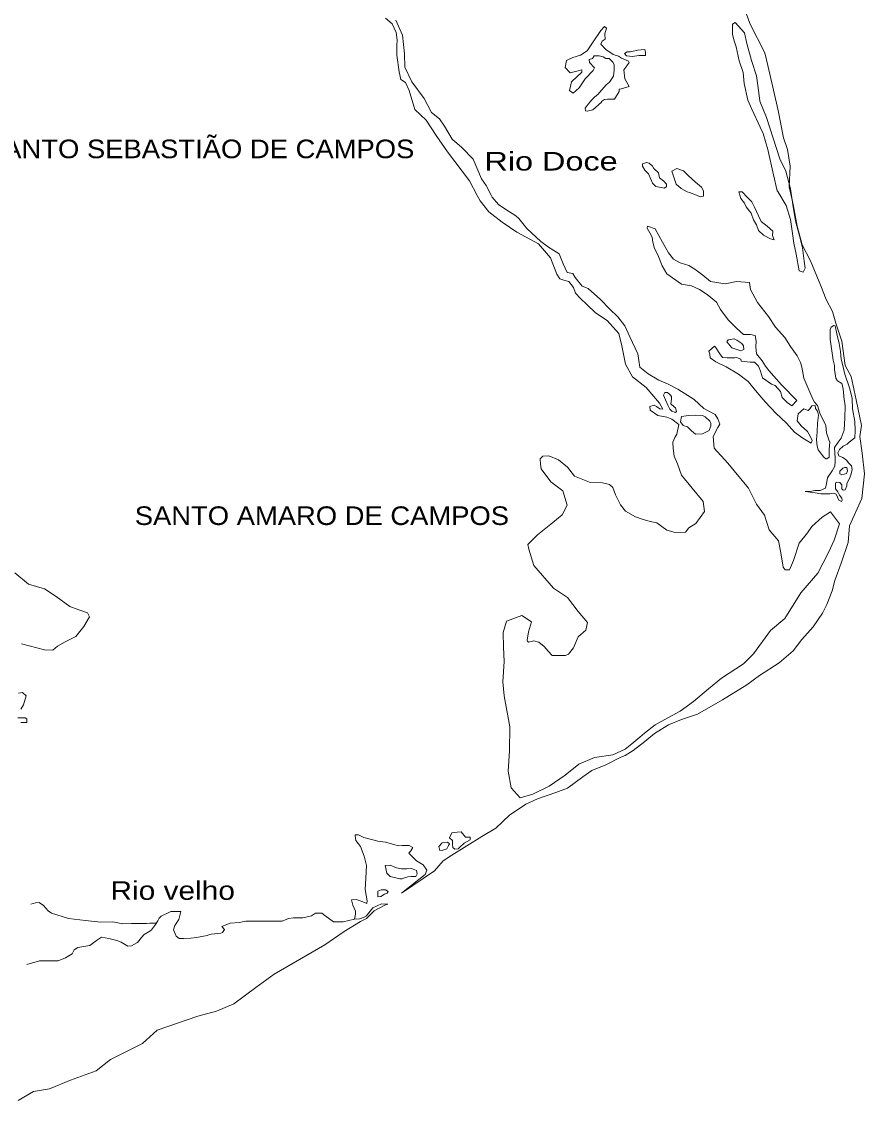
# Model space of a CAD drawing. Extents: x 47169 to 972804, y 7447977 to 9608469.
# Drawn here: x 267595 to 296306, y 7548738 to 7585503 of the extents above; entities that cross this region are included whole.
import ezdxf

# ---------------------------------------------------------------- set-up
doc = ezdxf.new("R2010")
doc.units = 0
doc.header["$LTSCALE"] = 270
doc.layers.add('1', color=7, linetype='Continuous', lineweight=13)
doc.layers.add('3', color=7, linetype='Continuous')

msp = doc.modelspace()

# ---------------------------------------------------------------- linework, layer by layer
at = {"layer": '1'}
for points in [[(278978.4, 7557599.3), (278967.3, 7557654.6), (278955.1, 7557787.3), (279068.7, 7557788.9), (279255.7, 7557702.9), (279732.4, 7557576.7), (279991.1, 7557536), (280270.9, 7557462.4), (280426.5, 7557409.2), (280560.5, 7557422.1), (280798, 7557425.4), (280922.8, 7557360.7), (280852.2, 7557237.9), (280791.3, 7557159.5), (281042.6, 7556908.2), (281271.7, 7556767.4), (281398.2, 7556580.9), (281338.3, 7556436.1), (280541.8, 7555804.7), (281656.5, 7556562.3), (281961.6, 7556898.9), (282248, 7557091.1), (283271.5, 7557736.6), (283752.8, 7558020.2), (284211.4, 7558458.4), (284774.2, 7558831.7), (285174.3, 7559014.4), (285790.9, 7559233.2), (286191.5, 7559382.6), (286712.9, 7559766.3), (287019.8, 7559980.9), (287502.4, 7560175.7), (288004.9, 7560437.2), (288159, 7560494.7), (288425.2, 7560664.4), (288823.8, 7560968.8), (289150.6, 7561239), (289632, 7561533.4), (290073.6, 7561716.5), (290618.4, 7561901), (291469.1, 7562388.5), (292298.8, 7562897.9), (292728.4, 7563213.7), (293404.2, 7563654.5), (293874, 7564059.4), (294168.4, 7564450.8), (294555.3, 7564876.8), (294879.7, 7565346.2), (295030.9, 7565636.1), (295210.7, 7566103.6), (295299.1, 7566459.1), (295518.7, 7567049), (295747.2, 7567749.7), (295801.9, 7568315.2), (296213.4, 7569250.9), (296305.8, 7570093.8), (296234.8, 7570790.6), (296144.8, 7571365.4), (296201.9, 7571742.7), (296025.3, 7572615.4), (295849.8, 7573410.5), (295648.6, 7573784.5), (295534.6, 7574613.7), (295330.4, 7575220.2), (295221.9, 7575617.5), (294999.5, 7576035.5), (294817.8, 7576498.3), (294465.7, 7577346.5), (294189.8, 7577896.7), (294016.2, 7578525.8), (293882.6, 7579266.1), (293776.4, 7579721), (293740.3, 7579873.4), (293772.6, 7580571.6), (293682.5, 7581146.3), (293553.2, 7581543.4), (293365.4, 7582471.2), (293156.6, 7583421), (293014.6, 7584006.2), (292915.9, 7584436.8), (292406.5, 7585438), (292224, 7585945.1)], [(279993.4, 7585614.8), (280223.5, 7585429.6), (280351.8, 7585132.4), (280386.4, 7584867), (280378.5, 7584689.7), (280383.1, 7584357.4)], [(288156.1, 7560705.1), (288380.9, 7560885.3), (288656.5, 7561121.6), (288819.9, 7561256.7), (289177.6, 7561538.4), (289505.6, 7561720), (290028.5, 7562003.9), (290488.8, 7562331.2), (290999.5, 7562758.9), (291438.6, 7563130.2), (292186.1, 7563616.3), (292522.5, 7563953), (293111.1, 7564747.1), (293591, 7565163.2), (294137.4, 7566034.2), (294717.4, 7566706.3), (295080.2, 7567408.8), (295271, 7567832.1), (295460, 7568388.4), (295155.2, 7568794.2), (294868.3, 7568613.3), (294510.8, 7568298.5), (294369.1, 7568075.2), (294084.4, 7567728.1), (293895.8, 7567138.6), (293755.4, 7566815.6), (293610.8, 7566813.7), (293537.2, 7566912.5), (293458.5, 7567398.8), (293380.9, 7567807.5), (293055.8, 7568179.8), (292904.5, 7568687.3), (292631, 7569060.3), (292355.3, 7569599.4), (291651.8, 7570454.1), (291190.4, 7570968.5), (291154.2, 7571366.8), (291315.5, 7571667.9), (291376, 7571779.5), (291311.6, 7571966.9), (291227, 7572109.8), (290831.7, 7572315), (290507.3, 7572620.9), (289954.9, 7572979), (289621.9, 7573151.8), (289299.8, 7573280.5), (288935.2, 7573497.1), (288653.2, 7573725.9), (288585.1, 7574179.1), (288318.9, 7574762.6), (288148.6, 7575136.9), (287906.8, 7575443.8), (287624, 7575716.9), (287320, 7576034), (286891.3, 7576404.9), (286693.7, 7576490.8), (286452, 7576786.6), (286377.9, 7576918.5), (286181.1, 7576949.1), (286042.7, 7577246.3), (285903.7, 7577587.8), (285549.2, 7577815.6), (285288.1, 7578011.4), (284806.7, 7578447.9), (284533.3, 7578787.6), (284428.5, 7578885.8), (284094.8, 7579102.8), (283844.5, 7579265.5), (283623.9, 7579517.3), (283588.9, 7579585.5), (283422.1, 7579913.3), (283263.9, 7580143.7), (282975.5, 7580815.4), (282587.6, 7581208.9), (282263.2, 7581492.4), (281998.5, 7581942.9), (281829.8, 7582184.3), (281557.9, 7582402), (281313.4, 7582886), (280892.1, 7583445.1), (280647.3, 7583951.3), (280641, 7584405.3), (280570.3, 7585035.7), (280346, 7585553.2)], [(293797.1, 7579721.3), (293782.5, 7579807.5), (293630, 7580403.6), (293428.2, 7580821.8), (292965.2, 7582233.5), (292740.8, 7582795.4), (292706.2, 7583071.8), (292626.2, 7583657.8), (292454, 7584176.1), (292301.5, 7584761.1), (292224.5, 7585114.5), (291899.2, 7585475.7), (291806.9, 7585419.1), (291808.5, 7585297.3), (291811.5, 7585064.8), (291866.1, 7584844), (291941.1, 7584645.6)], [(280383.1, 7584357.4), (280453, 7583793.5), (280518.7, 7583528.6), (280675.1, 7583431.1), (280792.7, 7583155.8), (280987.8, 7582505), (281375.3, 7582144.8), (281713.4, 7581617.8), (282103.5, 7581069.3), (282851.3, 7580071.6), (283112.4, 7579579), (283212.1, 7579389.9), (283506.7, 7579017.3), (283966.3, 7578669.1), (284467.2, 7578321.5), (285206.5, 7577932.8), (285616.1, 7577451), (285830.3, 7576900), (285925.5, 7576735.2), (286070.8, 7576692.9), (286236.9, 7576639.7), (286394.6, 7576442.5), (286459.3, 7576244), (286637.4, 7576069.2)], [(291941.1, 7584645.6), (292040.5, 7584159.6), (292180.1, 7583762.7), (292205.6, 7583397.5), (292337.2, 7582823.3), (292475.6, 7582515), (292752.3, 7581909.5)], [(292752.3, 7581909.5), (292858.6, 7581689.4), (293020.7, 7581148.8), (293207.8, 7580276.3), (293338.9, 7579735.3), (293351.6, 7579715.5)], [(290827.5, 7579682.5), (290826.8, 7579735.6), (290752.8, 7579856.5), (290554.1, 7580031.1), (290313.4, 7580249.4), (290145.9, 7580413.3), (289917.3, 7580498.9), (289742.7, 7580408), (289817.9, 7580198.5), (289893.3, 7579967), (290060.7, 7579814.1), (290268.9, 7579706.1), (290351, 7579676.2), (290591, 7579588.5)], [(290591, 7579588.5), (290715.7, 7579534.8), (290829.1, 7579558.4), (290827.5, 7579682.5)], [(293351.6, 7579715.5), (293645.2, 7579240.9), (293785.9, 7578755.4), (293854.1, 7578280), (293899.7, 7577948.4), (293977, 7577572.8), (294087.6, 7577009.4), (294222.5, 7576966.8), (294282.8, 7577100.5), (294248.7, 7577343.7), (294191.1, 7577797.1), (294092.8, 7578205.6), (293962.1, 7578713.4), (293872.3, 7579266), (293797.1, 7579721.3)], [(293790.5, 7574424.9), (293590.1, 7574732.5), (293275.4, 7575093.8), (293032.9, 7575456.2), (292665, 7575927.6), (292421.6, 7576367.4), (292387.4, 7576610.7), (291952.8, 7576649.3), (291561.1, 7576566.6), (291063.9, 7576648.7), (290802.7, 7576855.6), (290531.2, 7577062.5), (290322.8, 7577192.7), (290032.2, 7577277.4), (289803.1, 7577407.3), (289634.8, 7577626.6), (289423.3, 7577989.3), (289179.5, 7578440.1), (288920, 7578525.3), (288910.5, 7578458.7), (288995.3, 7578304.8), (289080, 7578150.8), (289102.9, 7577985), (289157.5, 7577764.2), (289263.7, 7577555.2), (289413.4, 7577180.6), (289572, 7576905.8), (290072.8, 7576558), (290414.7, 7576496.1), (290685, 7576377.9), (290945.7, 7576204.1), (291269.5, 7575942.5), (291407.2, 7575689.6), (291659.9, 7575338.5), (291953, 7575054.4), (292183.2, 7574835.9), (292420.9, 7574839), (292586.7, 7574808), (292620.3, 7574609), (292602.1, 7574420.5), (292625.9, 7574177.2), (292825.4, 7573936.1), (292931.1, 7573760.3), (293046.6, 7573617.8), (293476.7, 7573125), (294000.4, 7572589.2), (293837.4, 7572409.8), (293670.6, 7572518.4), (293503, 7572693.4), (293448.8, 7572892.1), (293270.4, 7573100.2), (293135.5, 7573142.7), (292833, 7573360.3), (292767.9, 7573592), (292693.4, 7573757.2), (292557.2, 7573899.4), (292412.6, 7573897.5), (292102.2, 7573926.6), (292090.8, 7574004), (291945.4, 7574057.5), (291893.9, 7574045.7), (291635.6, 7574042.3), (291470.1, 7574051.2), (291375.4, 7574182.9), (291227.8, 7574402.5), (291196.2, 7574446.4), (291002.2, 7574266.6), (291034.5, 7574167.3), (291046.5, 7574045.7), (291244.7, 7573904.3), (291598.3, 7573731.7), (292015, 7573482.5), (292349, 7573232.1), (292653.5, 7572859.5), (292926.3, 7572541.9), (293282.7, 7572158.9), (293648.7, 7571820.4), (293921.4, 7571513.8), (294203, 7571307), (294494.6, 7571133.6), (294524.5, 7571222.6), (294460.5, 7571376.8), (294365.5, 7571530.7), (294145.9, 7571727.2), (294019.6, 7571902.7), (294047.6, 7572135.7), (294241.7, 7572304.3), (294387.1, 7572250.9), (294448.4, 7572307), (294516.9, 7572406.9), (294625.9, 7572420.6), (294639.5, 7572320.3), (294703.1, 7572229.2), (294740.5, 7572089.3), (294713, 7571823.1), (294696.2, 7571523.9), (294668.8, 7571246.6), (294692.2, 7571036.5), (294735.2, 7570904.2), (294924.3, 7570663), (294987.2, 7570597.3)], [(286637.4, 7576069.2), (286846.9, 7575861.5), (287140.1, 7575577.5), (287546.7, 7575317.1), (287935.1, 7574868.2), (288044.1, 7574448.8), (288166, 7573830.2), (288409.5, 7573401.5), (288869.1, 7573031), (289330.9, 7572494.5), (289436.9, 7572296.5), (289333.4, 7572306.2), (289218.8, 7572382.2), (289145.9, 7572425.6), (289001.7, 7572390.4), (289003.4, 7572257.5), (289274.4, 7572083.9), (289574.9, 7572021.5), (289741.1, 7571957.2), (289981.2, 7571772.1), (289913.3, 7571439), (289852.8, 7571327.4), (289782.5, 7571171.4), (289785.5, 7570949.9), (289830.2, 7570695.8), (289937, 7570431.4), (290076.4, 7570045.6), (290433.5, 7569607.3), (290811.5, 7569147.1), (290857.4, 7568804.4), (290563.2, 7568401.7), (290327.5, 7568254.6), (290205.6, 7568098), (289864.8, 7568093.4), (289574.5, 7568167.1), (289230.3, 7568417.2), (289002.3, 7568469.6), (288732.7, 7568543.5), (288504.3, 7568629.1), (288171.1, 7568824), (287992.6, 7569032), (287822.8, 7569373.1), (287736.7, 7569626.7), (287621.7, 7569724.8), (287383.3, 7569788.1), (286938.8, 7569804.2), (286429.8, 7570007.8), (286188, 7570314.7), (285884.9, 7570565.3), (285552.4, 7570704.8), (285356.3, 7570691.1), (285264.5, 7570601.2), (285266.9, 7570424), (285300.2, 7570258.4), (285626.4, 7569819.7), (286033.5, 7569515.1), (286184.8, 7569018.8), (286013.6, 7568695.2), (285625.3, 7568379.8), (285165.4, 7568008.1), (284839.3, 7567682.4), (284872.4, 7567527.8), (285045.3, 7566965.3), (285716.8, 7566199.1), (286196.4, 7565873.3), (286554, 7565401.9), (286868.9, 7565029.5), (286810.5, 7564762.9), (286555.3, 7564538), (286395.2, 7564159.2), (286222.5, 7563946.4), (286119.9, 7563900.7), (285665.5, 7563894.6), (285529.1, 7564047.8), (285392.8, 7564201), (285215.1, 7564353.6), (285049.3, 7564395.7), (284864, 7564348.8), (284832.4, 7564392.7), (284821.7, 7564425.8), (284859.2, 7564703.2), (284968.1, 7565048.1), (284634.6, 7565265), (284110.5, 7565069.6), (284002.2, 7564680.4), (284009, 7564182.1), (284036.4, 7563695.1), (283994.1, 7563007.8), (284031.8, 7562521), (284232.1, 7561471.5), (284212.3, 7560651.5), (284170.3, 7559953.2), (284270.9, 7559389.7), (284575, 7559050.5), (285006.9, 7559178.2), (285571, 7559451.7), (286113.2, 7559824.6), (286583.2, 7560196.5), (287106.7, 7560425.1), (287735.4, 7560511.1), (288156.1, 7560705.1)], [(294987.2, 7570597.3), (295028.5, 7570597.9), (295100.1, 7570654.2), (295109.7, 7570709.7), (295108.1, 7570831.5), (295107, 7570920), (295124.3, 7571175), (295092.3, 7571252.1), (295017, 7571483.7), (294993.1, 7571738.2), (294791.3, 7572156.4), (294705.2, 7572421.1), (294610.8, 7572530.6), (294547.4, 7572640.6), (294238.5, 7573345.4), (294171.7, 7573721.1), (294128.2, 7573886.6), (294011.6, 7574106.6), (293790.5, 7574424.9)], [(267362.5, 7566714.7), (267833, 7566333.9), (268372.6, 7566175.7), (268769, 7565915.6), (269238.9, 7565568), (269540.1, 7565461.7), (269841.2, 7565355.3), (269905.1, 7565223.3), (269713.7, 7564888.2), (269439.7, 7564551.9), (269080.8, 7564369.4), (268814.4, 7564221.5), (268661.5, 7564086.3), (268372.2, 7564093.1), (267594.5, 7564292.2)], [(267484.9, 7562617.9), (267629.1, 7562642.1), (267754.8, 7562522.1), (267656, 7562221.6), (267565.2, 7562076.2)], [(267466.3, 7561775.7), (267714.2, 7561779.4), (267776.8, 7561736), (267777.7, 7561669.5), (267778.6, 7561614.1), (267665, 7561612.5), (267572, 7561611.1)], [(267483.8, 7548737.7), (268005.6, 7549044.5), (268551.2, 7549130.2), (269258.9, 7549428.6), (270131.5, 7549740.5), (270621.1, 7550135.4), (271717.6, 7550672), (272216.6, 7551133.5), (273603, 7551607.7), (274230.1, 7551782.9), (274825.2, 7552024.1), (275570.6, 7552588.6), (276193.8, 7553040.6), (277924, 7554039.9), (278588.6, 7554492.4), (279141.2, 7554832.5), (279346.2, 7554935), (279600.7, 7555193.4), (279990.1, 7555398.2), (280072.3, 7555421.5), (279855.3, 7555440.6), (279557.8, 7555303.5), (279375.3, 7555068.4), (279345, 7555023.6), (279242.5, 7554966.8), (279139.8, 7554932.1), (279109, 7554920.6), (278933.5, 7554918.2), (278972.5, 7555084.9), (278971.1, 7555184.5), (278875.2, 7555393.6), (278831.5, 7555570.2), (278996.4, 7555583.6), (279162.4, 7555530.6), (279359.7, 7555444.8), (279368.6, 7555544.6), (279301.3, 7555931.3), (279316.6, 7556308.1), (279341.5, 7556740.5), (279264.8, 7557060.6), (279136.2, 7557391.1), (278978.4, 7557599.3)], [(272184.3, 7554777.4), (271967.6, 7554774.2), (271854, 7554772.6), (271637.3, 7554769.5), (271338, 7554765.1), (271038.7, 7554760.7), (270707.4, 7554822.4), (270294.6, 7554816.3), (269777.7, 7554864.2), (269198.6, 7554933.2), (268617.7, 7555124), (268503, 7555199.9), (268345.5, 7555374.8), (268199.4, 7555483.4), (268065.4, 7555470.4), (267911.2, 7555423.8)], [(278933.5, 7554918.2), (278552.9, 7554824.2), (278222.7, 7554819.5), (277920.2, 7555036.8), (277826.1, 7555124.1), (277609.3, 7555121), (277476.4, 7555030.5), (277178.1, 7554959.8), (276858.1, 7554955.3), (276682.8, 7554941.7), (276467.3, 7554850), (276199, 7554846.2), (275941, 7554842.5), (275600.2, 7554848.7), (275239, 7554843.6), (275012.6, 7554796), (274703.1, 7554780.5), (274610.7, 7554745.9), (274415.7, 7554665.6), (274510, 7554567.3), (274439.4, 7554455.5), (274377.8, 7554432.4), (274047.8, 7554405.5), (273996.4, 7554393.7), (273914.3, 7554359.3), (273554, 7554287.7), (273358.2, 7554262.7), (273120.9, 7554259.2), (272966.1, 7554257), (272861.7, 7554333), (272765.7, 7554553.2), (272815.2, 7554697.9), (272956.8, 7554899.4), (273014.7, 7555177.1), (272911.5, 7555175.6), (272684.4, 7555172.3), (272346.1, 7555012.4), (272285.1, 7554945), (272234.8, 7554855.7), (272154, 7554732.7), (272022.4, 7554553.5), (271961.1, 7554508.3), (271766.6, 7554394.7), (271675.2, 7554293.7), (271543.6, 7554114.5), (271338.8, 7554000.8), (271214.9, 7553999), (270986, 7554128.6), (270840.5, 7554192.9), (270571.2, 7554255.4), (270322.8, 7554296.1), (270149, 7554182.8), (269924.4, 7554013.4), (269512.4, 7553951.9), (269389.7, 7553872.6), (269319.4, 7553738.6), (269094.4, 7553591.3), (268837.7, 7553498.9), (268507.5, 7553494), (268208.2, 7553489.6), (267776.3, 7553372.5)]]:
    msp.add_lwpolyline(points, dxfattribs=at)
for points in [[(287624.2, 7583436.7), (287511.7, 7583346.6), (287226.5, 7583021.6), (287124.1, 7582942.7), (287022.1, 7582841.7), (286900.1, 7582685), (286798.5, 7582550.7), (286799.7, 7582462.1), (286861.8, 7582451.9), (287057.7, 7582498.8), (287354.1, 7582757.5), (287353.8, 7582779.7), (287456.3, 7582847.5), (287559.5, 7582859.9), (287631.9, 7582860.9), (287797.3, 7582863.1), (287949, 7583119.9), (287947.9, 7583197.4), (288020.2, 7583209.4), (288288, 7583290.5), (288139.7, 7583554.4), (288115, 7583853.1), (288216.5, 7583998.4), (288297.7, 7584110.2), (288266.1, 7584154.1), (288027, 7584250.6), (287932.9, 7584326.9), (287746, 7584379.8), (287495.5, 7584553.7), (287327.7, 7584728.6), (287367.6, 7584839.9), (287470.1, 7584907.7), (287467.8, 7585084.9), (287516.9, 7585273.9), (287454, 7585339.5), (287331.9, 7585193.9), (287068.1, 7584813.8), (286865.4, 7584500.9), (286639.9, 7584353.9), (286371.9, 7584283.9), (286156.1, 7584181.3), (286107.7, 7583937), (286286, 7583751.1), (286512.7, 7583809.5), (286677.6, 7583856), (286678.6, 7583778.5), (286331.4, 7583452.6), (286263, 7583152.7), (286388.3, 7583065.8), (286592.7, 7583245.7), (286795.5, 7583547.5), (287070.8, 7583839.1), (287110.9, 7583928.3), (286943.1, 7584103.2), (286931.3, 7584213.9), (287044.6, 7584248.6), (287105.4, 7584338), (287270.9, 7584340.2), (287405.9, 7584297.7), (287499.7, 7584243.6), (287613.4, 7584245.1), (287739.1, 7584125), (287781.6, 7584036.9), (287784.2, 7583848.7), (287756, 7583637.9)], [(288408.8, 7584311.1), (288201.7, 7584330.5), (288138.5, 7584418.2), (288220.5, 7584474.7), (288334.2, 7584476.2), (288571.4, 7584523.7), (288829.6, 7584549.3), (288851.6, 7584449.9), (288853, 7584350.2), (288625.5, 7584347.2)], [(288822.2, 7580440.1), (288748, 7580572), (288747, 7580649.5), (288880.8, 7580695.6), (288974.1, 7580674.7), (289089.2, 7580576.5), (289131.5, 7580499.6), (289288.6, 7580346.6), (289321.9, 7580180.9), (289468.2, 7580061), (289562.5, 7579962.6), (289563.6, 7579885.1), (289491.9, 7579828.7), (289201.8, 7579880.3), (289086.5, 7580000.6), (289033, 7580132.8), (288948, 7580308.9)], [(292992.8, 7578534.6), (293191.4, 7578360), (293172.7, 7578215.8), (293226.4, 7578061.4), (293101.7, 7578104.1), (292872.8, 7578222.9), (292694.9, 7578386.8), (292630.5, 7578574.2), (292524.8, 7578750), (292449.5, 7578970.5), (292386.5, 7579047.2), (292281.3, 7579189.9), (292217.7, 7579310.9), (292091.4, 7579475.3), (292026.5, 7579696), (292140.2, 7579697.5), (292307.9, 7579522.5), (292475.5, 7579358.5), (292560.5, 7579182.4), (292698.8, 7578885.2), (292794.4, 7578687.1)], [(294288.7, 7569491.8), (294453.9, 7569493.9), (294618.9, 7569518.2), (294794.5, 7569520.5), (294979.4, 7569600.4), (295018.7, 7569756), (295047.1, 7569955.7), (295077.4, 7570011.5), (295138.4, 7570089.8), (295209.4, 7570190.4), (295300.4, 7570346.6), (295308.4, 7570523.9), (295307.1, 7570623.6), (295294.5, 7570800.6), (295292.1, 7570988.9), (295413.7, 7571167.7), (295515.3, 7571301.9), (295615, 7571580.1), (295640.6, 7572001.3), (295645.7, 7572411.1), (295600.5, 7572709.6), (295598.2, 7572886.8), (295565.2, 7573041.4), (295532.5, 7573173.9), (295386.7, 7573260.6), (295333.9, 7573348.5), (295288.7, 7573647), (295287, 7573779.8), (295243.2, 7573967.5), (295141.1, 7574675), (295138.6, 7574863.3), (295136.8, 7575007.2), (295177.1, 7575085.3), (295259, 7575141.7), (295310.9, 7575131.3), (295365.9, 7574866.2), (295442.6, 7574535), (295487.5, 7574258.7), (295511.6, 7573993.2), (295576.9, 7573739.3), (295631.4, 7573518.5), (295803.5, 7572989.1), (295890.5, 7572657.9), (295905.4, 7572303.7), (295983.2, 7571872.8), (295987.2, 7571562.7), (295980, 7571319), (295785.6, 7571172.5), (295714.2, 7571105.1), (295580.7, 7571036.9), (295458.2, 7570924.6), (295397.8, 7570802), (295430.1, 7570702.7), (295575.4, 7570649.2), (295700.5, 7570562.2), (295774.3, 7570452.4), (295868.4, 7570365), (295890.6, 7570243.5), (295841.5, 7570043.5), (295801.6, 7569932.2), (295710.8, 7569765), (295712, 7569676.4), (295651.7, 7569542.7), (295579.5, 7569530.7), (295537.7, 7569574.4), (295535.8, 7569718.4), (295472.8, 7569795.1), (295369.4, 7569804.8), (295318, 7569782), (295320.6, 7569582.7), (295404.7, 7569473), (295457.7, 7569363), (295541.7, 7569264.4), (295552.9, 7569198.1), (295522.4, 7569153.4), (295428.9, 7569196.5), (295343.7, 7569394.7), (295260.6, 7569426.9), (295126.5, 7569414), (295012.9, 7569412.6), (294816.6, 7569410), (294630.2, 7569440.8)], [(292135.5, 7574536.2), (292188.3, 7574448.3), (292200.3, 7574326.6), (292087.2, 7574280.9), (291993.8, 7574312.9), (291786.1, 7574387.7), (291618.1, 7574584.8), (291668.8, 7574663), (291864.8, 7574687.7), (291958.4, 7574644.7)], [(289747.9, 7572223.1), (289674.5, 7572299.7), (289610.8, 7572431.7), (289525.8, 7572607.8), (289461.6, 7572773.1), (289501.7, 7572862.3), (289594.7, 7572863.5), (289688.7, 7572787.2), (289730.9, 7572721.3), (289732.1, 7572632.7), (289713.5, 7572477.4), (289828.5, 7572379.3), (289870.4, 7572335.5), (289903, 7572214.1), (289872.4, 7572180.5)], [(291017.2, 7571564.3), (290791.4, 7571450.6), (290553.8, 7571447.4), (290418, 7571556.4), (290282, 7571687.5), (290136.6, 7571741), (290042, 7571861.5), (290070.7, 7572039.1), (290318.2, 7572075.6), (290545.3, 7572089.7), (290793.4, 7572081.9), (290876.6, 7572038.7), (291044, 7571885.9), (291075.9, 7571819.8), (291077, 7571731.2)], [(295541.7, 7570061.8), (295469, 7570094.1), (295467.8, 7570182.7), (295569.8, 7570283.7), (295641.8, 7570306.7), (295703.8, 7570307.5), (295725.9, 7570197.1), (295696.2, 7570097)], [(282522.8, 7557371.9), (282472, 7557315.8), (282348.3, 7557303), (282285.6, 7557357.5), (282273.7, 7557468.1), (282272, 7557589.9), (282167.4, 7557688.1), (282247.7, 7557855.4), (282433.2, 7557880.1), (282567.3, 7557893), (282714.4, 7557706.8), (282879.5, 7557709.1), (282880.8, 7557620.5), (282675.8, 7557506.9)], [(282140.2, 7557421.9), (282079.8, 7557310.3), (281946.2, 7557264.2), (281843.1, 7557251.7), (281810.2, 7557395.2), (281922, 7557518.6), (282107.5, 7557543.3), (282170.4, 7557477.7)], [(280881.2, 7556640.2), (281047.2, 7556576), (281069.6, 7556454.5), (281029.5, 7556365.3), (280936.6, 7556364), (280864.4, 7556363), (280750.9, 7556361.4), (280637.8, 7556326.6), (280545.3, 7556292.1), (280483.4, 7556291.2), (280152, 7556364.1), (280036.8, 7556484.4), (279981.6, 7556738.4), (280146.6, 7556751.7), (280364.6, 7556666.2), (280540.7, 7556624.3), (280716.2, 7556626.8)], [(280046.4, 7555797.8), (279954, 7555763.2), (279831.2, 7555684), (279728.2, 7555671.5), (279725.4, 7555870.8), (279848.6, 7555916.8), (279993.1, 7555918.9), (280086.9, 7555853.7)]]:
    msp.add_lwpolyline(points, close=True, dxfattribs=at)

# ---------------------------------------------------------------- texts
at = {"layer": '3'}
for s, height, width, p in [('SANTO SEBASTIÃO DE CAMPOS', 634.6, 1.1, (266347.4, 7580846.5)), ('Rio Doce', 634.5, 1.3, (283362.9, 7580427)), ('SANTO AMARO DE CAMPOS', 634.1, 1.1, (271450.7, 7568347.3)), ('Rio velho', 633.6, 1.2, (270624.2, 7555574.4))]:
    msp.add_text(s, height=height, dxfattribs=dict(at, width=width)).set_placement(p)

doc.saveas('drawing.dxf')
